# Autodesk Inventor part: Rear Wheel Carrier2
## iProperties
Shininess: 77.0
Angle Display Precision: 2
Document Length Units: 11269
Document Angle Units: 11279
Document Time Units: 11290
Document Mass Units: 11283
Document Length Units Precision: 3
Document Angle Units Precision: 2
Compacted: True
Created: 2001-08
Part Number: Rear Wheel Carrier2
Document SubType Name: Modeling
Designer: rak
Description: Rear Wheel Carrier
Density: 0.0
Volumn: 0.0
Area: 0.0
PropertySet Name: Model Information
Control State: 0
Master: False
Checked Out: False
Author: rak
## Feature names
1. Extrusion1
2. Chamfer1
3. Extrusion2
4. Chamfer2
5. Chamfer3
6. Circular Pattern1
7. Chamfer4
8. Extrusion3
9. Hole1
10. Extrusion4
